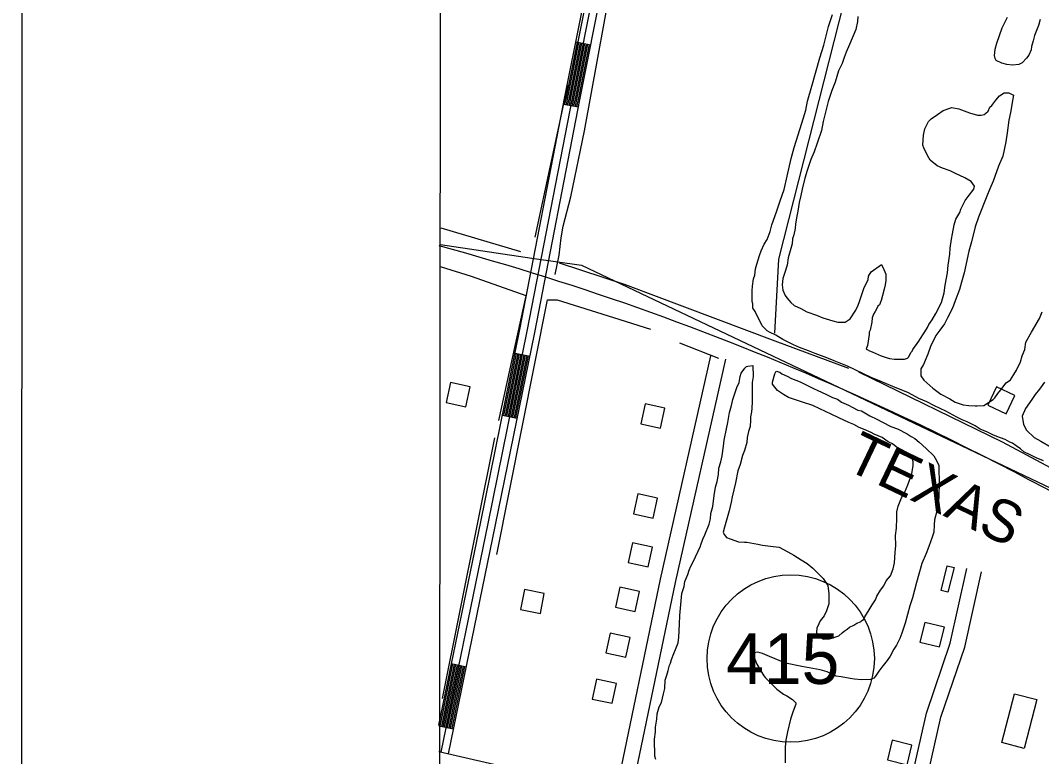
# Model space of a CAD drawing. Extents: x 3250478 to 3288318, y 788638 to 816472.
# Drawn here: x 3253812 to 3255826, y 797765 to 799216 of the extents above; entities that cross this region are included whole.
import ezdxf

# ---------------------------------------------------------------- set-up
doc = ezdxf.new("R2010")
doc.units = 0
for name, color, linetype in [('V-ANNO-SYMB', 7, 'Continuous'), ('V-BLDG-OTLN', 7, 'Continuous'), ('V-GRID-FRAM', 7, 'Continuous'), ('V-RAIL-IDEN', 7, 'Continuous'), ('V-RAIL-TRAK', 7, 'Continuous'), ('V-ROAD-CNTR', 7, 'Continuous'), ('V-ROAD-IDEN', 7, 'Continuous'), ('V-SITE-VEGE', 7, 'Continuous'), ('V-TOPO-SHOR', 7, 'Continuous')]:
    doc.layers.add(name, color=color, linetype=linetype)

msp = doc.modelspace()

# ---------------------------------------------------------------- linework, layer by layer
at = {"layer": 'V-ANNO-SYMB'}
msp.add_lwpolyline([(3253811.8, 789856.3), (3286895, 789846.6), (3286901.6, 812763.2), (3253818.4, 812772.8), (3253811.8, 789856.3)], dxfattribs=at)
at = {"layer": 'V-BLDG-OTLN'}
for points in [[(3254690.2, 798454.9), (3254698.8, 798494), (3254659.7, 798502.5), (3254651.1, 798463.4)], [(3255719.5, 798458.1), (3255755.7, 798441.1), (3255772.7, 798477.3), (3255736.5, 798494.3)], [(3255074.2, 798412.9), (3255082.7, 798452), (3255043.7, 798460.5), (3255035.1, 798421.4)], [(3255059.7, 798235.5), (3255068.2, 798274.6), (3255029.2, 798283.1), (3255020.6, 798244.1)], [(3255049.6, 798139.3), (3255058.1, 798178.4), (3255019.1, 798186.9), (3255010.5, 798147.9)], [(3255627.4, 798092.9), (3255639.3, 798141.5), (3255652.9, 798138.2), (3255641, 798089.6)], [(3254805.6, 798094.6), (3254798, 798055.3), (3254837.3, 798047.7), (3254844.9, 798087)], [(3255024.1, 798051.5), (3255032.7, 798090.6), (3254993.6, 798099.1), (3254985.1, 798060)], [(3255624.5, 797981.5), (3255634.1, 798020.3), (3255595.3, 798030), (3255585.6, 797991.1)], [(3255005.5, 797961.2), (3255014.1, 798000.3), (3254975, 798008.8), (3254966.5, 797969.8)], [(3254978.6, 797870.4), (3254987.2, 797909.5), (3254948.1, 797918), (3254939.6, 797878.9)], [(3255747, 797793), (3255772.3, 797889.3), (3255816.4, 797877.8), (3255791.1, 797781.4)], [(3255560.4, 797749), (3255570, 797787.9), (3255531.2, 797797.5), (3255521.6, 797758.7)]]:
    msp.add_lwpolyline(points, close=True, dxfattribs=at)
at = {"layer": 'V-GRID-FRAM'}
msp.add_lwpolyline([(3254649.6, 812209.1), (3286070.1, 812200), (3286072.7, 794013.5), (3254636.4, 794022.7), (3254649.6, 812209.1)], dxfattribs=at)
at = {"layer": 'V-RAIL-TRAK'}
msp.add_line((3255451.1, 798480.9), (3256028, 798207), dxfattribs=at)
for points in [[(3254639.9, 798774.5), (3254820.5, 798748)], [(3254820.5, 798748), (3254918.5, 798733.7), (3255451.1, 798480.9)]]:
    msp.add_lwpolyline(points, dxfattribs=at)
at = {"layer": 'V-ROAD-CNTR'}
for p, q in [((3254907.2, 799174.2), (3254936.6, 799168.3)), ((3254882.8, 799051.5), (3254912.2, 799045.8)), ((3254787.3, 798560.8), (3254816.7, 798554.8)), ((3254762.3, 798438.4), (3254791.7, 798432.4)), ((3254661.9, 797948.6), (3254691.3, 797942.5)), ((3254637, 797826.1), (3254666.1, 797820.1))]:
    msp.add_line(p, q, dxfattribs=at)
for points in [[(3254637, 797827.5), (3254719.5, 798228.1), (3254796.7, 798606.9), (3254885.6, 799065.9), (3254977.9, 799527.7), (3255097.9, 800111.1), (3255272.1, 801014.2)], [(3254641.3, 797774.2), (3254734.2, 798225.1), (3254811.4, 798604), (3254900.3, 799063), (3254992.6, 799524.7), (3255112.7, 800108.2), (3255286.8, 801011.4)], [(3254656, 797771.1), (3254748.9, 798222.1), (3254826.1, 798601.1), (3254915, 799060.1), (3255007.3, 799521.7), (3255127.4, 800105.2), (3255301.6, 801008.5)], [(3254885.7, 799050.9), (3254888.5, 799065.3), (3254910.2, 799173.6)], [(3254888.7, 799050.3), (3254891.4, 799064.7), (3254913.1, 799173)], [(3254891.6, 799049.8), (3254894.4, 799064.1), (3254916, 799172.4)], [(3254894.6, 799049.2), (3254897.3, 799063.6), (3254919, 799171.8)], [(3254897.5, 799048.6), (3254900.3, 799063), (3254921.9, 799171.2)], [(3254900.4, 799048.1), (3254903.2, 799062.4), (3254924.9, 799170.6)], [(3254903.4, 799047.5), (3254906.2, 799061.8), (3254927.8, 799170)], [(3254906.3, 799046.9), (3254909.1, 799061.2), (3254930.8, 799169.5)], [(3254909.3, 799046.3), (3254912.1, 799060.7), (3254933.7, 799168.9)], [(3254765.3, 798437.8), (3254790.3, 798560.2)], [(3254768.2, 798437.2), (3254793.2, 798559.6)], [(3254771.2, 798436.6), (3254796.1, 798559)], [(3254774.1, 798436), (3254799.1, 798558.4)], [(3254777, 798435.4), (3254802, 798557.8)], [(3254780, 798434.8), (3254805, 798557.2)], [(3254782.9, 798434.2), (3254807.9, 798556.6)], [(3254785.9, 798433.6), (3254810.8, 798556)], [(3254788.8, 798433), (3254813.8, 798555.4)], [(3255172.8, 798555.4), (3255073.6, 798114.9), (3254986.1, 797694.9)], [(3255202.1, 798548.8), (3255102.9, 798108.5), (3255015.5, 797688.8)], [(3255536, 797575.4), (3255598.3, 797850.9), (3255645, 797989.1), (3255678, 798136.4)], [(3255565.3, 797568.8), (3255627.2, 797842.8), (3255674, 797981), (3255707.3, 798129.8)], [(3254639.6, 797825.5), (3254664.8, 797948)], [(3254642.6, 797824.9), (3254667.8, 797947.4)], [(3254645.5, 797824.3), (3254670.7, 797946.8)], [(3254648.4, 797823.7), (3254673.7, 797946.2)], [(3254651.4, 797823.1), (3254676.6, 797945.6)], [(3254654.3, 797822.5), (3254679.5, 797944.9)], [(3254657.2, 797821.9), (3254682.5, 797944.3)], [(3254660.2, 797821.3), (3254685.4, 797943.7)], [(3254663.1, 797820.7), (3254688.3, 797943.1)], [(3254636.9, 797775.2), (3254947.7, 797703.6), (3255403.4, 797603), (3255700, 797540.9)]]:
    msp.add_lwpolyline(points, dxfattribs=at)
for centre, radius, start, end in [((3253165.2, 793365.4), 5603.5, 65.816, 74.7649), ((3252927.2, 792861), 6161.2, 55.44711, 65.71922)]:
    msp.add_arc(centre, radius, start, end, dxfattribs=at)
at = {"layer": 'V-ROAD-IDEN'}
msp.add_circle((3255330.8, 797958.6), 165, dxfattribs=at)
msp.add_circle((3255330.8, 797958.6), 165, dxfattribs=at)
at = {"layer": 'V-SITE-VEGE'}
for points in [[(3255829.3, 798348.1), (3255814.9, 798354.2), (3255803.2, 798360.3), (3255790.6, 798366.4), (3255784.3, 798371.7), (3255775.3, 798377.9), (3255768.1, 798383.1), (3255762.7, 798384.9), (3255753.7, 798390.1), (3255744.7, 798393.6), (3255737.5, 798396.2), (3255729.4, 798399.7), (3255718.7, 798404.9), (3255704.3, 798411), (3255694.4, 798417.2), (3255679.1, 798425), (3255669.2, 798429.4), (3255658.4, 798434.6), (3255636.8, 798446), (3255614.3, 798456.5), (3255599, 798464.4), (3255583.7, 798471.3), (3255563, 798482.7), (3255532.5, 798494.9), (3255507.3, 798505.3), (3255489.4, 798512.3), (3255442.6, 798535), (3255416.5, 798545.4), (3255402.1, 798551.5), (3255378.8, 798560.2), (3255366.2, 798565.4), (3255348.3, 798571.5), (3255336.6, 798576.7), (3255315, 798587.2), (3255301.5, 798596), (3255288.9, 798602.1), (3255284.4, 798604.7), (3255274.4, 798614.4), (3255260.7, 798642.9), (3255258, 798646.4), (3255256.1, 798649.1), (3255256, 798658.1), (3255255.1, 798662.5), (3255254.9, 798683.1), (3255255.6, 798692.9), (3255257.3, 798707.3), (3255259.9, 798714.4), (3255261.5, 798727), (3255264.1, 798736), (3255269.2, 798753), (3255272.7, 798762), (3255278.8, 798775.5), (3255284.1, 798784.5), (3255290.2, 798800.6), (3255293.6, 798813.2), (3255303.1, 798839.3), (3255310, 798860.8), (3255317.8, 798883.2), (3255323.8, 798909.3), (3255331.4, 798944.2), (3255337.4, 798965.8), (3255353, 799014.2), (3255360.7, 799039.4), (3255364.1, 799057.3), (3255372.7, 799086.9), (3255388.2, 799142.5), (3255395.9, 799167.7), (3255405.3, 799204.4), (3255413.1, 799227.8)], [(3255463.2, 799223.9), (3255462.5, 799214), (3255459.1, 799198.8), (3255446.9, 799169.1), (3255439.9, 799153.9), (3255436.5, 799143.1), (3255432.1, 799131.4), (3255425.1, 799117), (3255418.2, 799094.6), (3255412.2, 799078.4), (3255404.4, 799056.9), (3255395, 799017.4), (3255391.6, 798999.5), (3255383, 798974.3), (3255376.9, 798957.3), (3255370.8, 798942), (3255363, 798920.4), (3255358.7, 798905.2), (3255353.6, 798883.7), (3255351.1, 798871.1), (3255347.6, 798857.7), (3255345.1, 798840.6), (3255342.6, 798830.8), (3255340.1, 798815.5), (3255339.3, 798806.6), (3255336.7, 798794), (3255334.2, 798786), (3255333.4, 798776.1), (3255330.8, 798767.1), (3255325.6, 798748.3), (3255324, 798734), (3255318.8, 798717.8), (3255315.4, 798707.9), (3255313.7, 798695.4), (3255315.6, 798684.7), (3255320.2, 798674), (3255323, 798669.6), (3255331.1, 798660.7), (3255337.5, 798654.5), (3255350.9, 798648.4), (3255362.6, 798642.3), (3255381.5, 798635.4)], [(3255822.8, 799218.2), (3255819.4, 799206.5), (3255811.6, 799186.8), (3255809, 799176), (3255805.6, 799165.2), (3255804.8, 799158.1), (3255800.4, 799148.2), (3255796, 799141.9), (3255787.2, 799132.8), (3255780.9, 799129.2), (3255768.4, 799128.1), (3255756.8, 799129.8), (3255746.9, 799132.4), (3255736.1, 799137.6), (3255734.3, 799141.2), (3255732.4, 799147.4), (3255734.1, 799159.9), (3255737.5, 799171.6), (3255747.9, 799202.1), (3255758.4, 799222.8)], [(3255381.5, 798635.4), (3255394.1, 798630.1), (3255413.8, 798624.1), (3255423.7, 798621.5), (3255438, 798621.7), (3255444.2, 798625.3), (3255447.8, 798628.1), (3255459.2, 798645.2), (3255463.6, 798655.1), (3255466.2, 798662.3), (3255472.2, 798680.2), (3255475.7, 798690.1), (3255483.5, 798705.4), (3255484.4, 798712.6), (3255489.6, 798720.7), (3255510, 798735.2), (3255514.6, 798725.4), (3255518.3, 798716.5), (3255518.4, 798704), (3255516.8, 798695), (3255515.1, 798687), (3255511.6, 798674.4), (3255509.1, 798664.6), (3255505.6, 798655.6), (3255502.9, 798652.9), (3255500.3, 798647.5), (3255497.7, 798643), (3255494.2, 798637.6), (3255491.6, 798630.4), (3255490.8, 798621.4), (3255487.4, 798606.2), (3255485.6, 798601.7), (3255485.7, 798597.2), (3255482.4, 798575.7), (3255479.8, 798569.4), (3255481.6, 798567.6), (3255486.1, 798565), (3255491.4, 798563.3), (3255509.4, 798555.4), (3255519.3, 798552), (3255525.6, 798550.3), (3255535.4, 798548.6), (3255555.1, 798548.8), (3255561.4, 798550.7), (3255564, 798553.4), (3255565.7, 798557.9), (3255568.4, 798562.4), (3255570.1, 798564.2), (3255571.9, 798567.8), (3255583.3, 798584), (3255586.8, 798589.4), (3255593, 798598.4), (3255595.6, 798602.9), (3255600.9, 798611.1), (3255603.5, 798617.3), (3255609.7, 798626.4), (3255616.7, 798639), (3255628.1, 798660.6), (3255633.2, 798679.4), (3255635.7, 798694.6), (3255639.9, 798718.8), (3255641.5, 798734.1), (3255644.8, 798755.6), (3255645.6, 798767.2), (3255648.1, 798785.1), (3255649.7, 798795.9), (3255653.1, 798813.8), (3255656.6, 798824.6), (3255664.5, 798838.1), (3255666.2, 798844.3), (3255674.9, 798861.4), (3255681.1, 798869.6), (3255691.7, 798884), (3255693.4, 798889.4), (3255687, 798899.1), (3255674.4, 798906.1), (3255655.5, 798914.9), (3255645.6, 798920.1), (3255630.4, 798925.3), (3255619.6, 798929.7), (3255606, 798941.1), (3255600.6, 798950), (3255593.2, 798965.1), (3255591.4, 798970.5), (3255592.9, 798990.2), (3255595.5, 799002.7), (3255602.5, 799017.1), (3255607.8, 799022.5), (3255620.2, 799030.7), (3255631.7, 799038.9), (3255648.7, 799044.5), (3255662.1, 799041.9), (3255683.7, 799034.1), (3255698.9, 799029.8), (3255706.1, 799029.9), (3255712.3, 799030.9), (3255715.9, 799033.6), (3255720.3, 799037.3), (3255723.8, 799045.3), (3255727.3, 799049), (3255735.2, 799058.9)], [(3255735.2, 799058.9), (3255742.3, 799067.9), (3255752.1, 799073.4), (3255761, 799073.5), (3255770, 799069.1), (3255769.2, 799062), (3255764.1, 799035.1), (3255760.7, 799019.8), (3255757.5, 798994.8), (3255755, 798976.8), (3255749, 798949), (3255740.3, 798929.3), (3255729.9, 798899.6), (3255723.8, 798884.4), (3255717.8, 798870), (3255701.2, 798828.7), (3255694.3, 798809.8), (3255687.5, 798780.2), (3255682.3, 798761.4), (3255673, 798719.2), (3255667.8, 798700.4), (3255663.5, 798686), (3255654.9, 798663.6), (3255649.6, 798649.2), (3255640, 798630.3), (3255633.9, 798618.6), (3255625.1, 798606), (3255617.2, 798595.1), (3255606.7, 798573.6), (3255601.5, 798558.3), (3255592.8, 798538.5), (3255587.5, 798529.5), (3255587.7, 798516.1), (3255593.2, 798507.2), (3255611.2, 798491.3), (3255626.6, 798479.9), (3255644.6, 798470.3), (3255655.4, 798464.1), (3255670.6, 798458.9), (3255682.3, 798457.3), (3255694.8, 798456.5), (3255698.4, 798456.6), (3255711.8, 798457.6), (3255730.4, 798469.5), (3255733.1, 798472.2), (3255739.2, 798481.2), (3255745.4, 798488.4), (3255756, 798502), (3255764, 798508.3), (3255771, 798518.2), (3255776.3, 798527.2), (3255784.1, 798543.4), (3255787.6, 798555.1), (3255792.8, 798567.7), (3255794.4, 798582), (3255805.8, 798601.8), (3255821.6, 798628.8), (3255826.8, 798642.3)], [(3255128, 798124.1), (3255130.9, 798132.9), (3255133.7, 798140.7), (3255138.5, 798149.6), (3255152.8, 798180.1), (3255153.7, 798183), (3255157.5, 798193.8), (3255161.3, 798202.6), (3255169.9, 798223.3), (3255172.7, 798234), (3255173.6, 798244.8), (3255177.3, 798258.5), (3255180, 798280.1), (3255182.7, 798296.7), (3255185.5, 798307.5), (3255188.3, 798321.2), (3255189.1, 798333.9), (3255192.9, 798346.7), (3255195.7, 798358.4), (3255198.4, 798377), (3255199.3, 798388.8), (3255203.9, 798411.3), (3255206.7, 798424.1), (3255210.4, 798443.7), (3255214.1, 798457.4), (3255216.9, 798469.1), (3255224.4, 798492.7), (3255229.2, 798502.5), (3255231, 798514.3), (3255232.9, 798521.1), (3255240.6, 798531), (3255243.5, 798534), (3255246.4, 798535), (3255256.2, 798536.1), (3255256.5, 798514.6), (3255254.6, 798502.8), (3255255.1, 798464.7), (3255254.2, 798452), (3255253.3, 798445.1), (3255251.5, 798435.3), (3255251.6, 798428.5), (3255250.7, 798415.8), (3255247.9, 798406), (3255245.1, 798394.2), (3255244.3, 798384.4), (3255239.6, 798368.7), (3255235.8, 798358.9), (3255231.1, 798341.3), (3255226.3, 798328.5), (3255221.7, 798305), (3255215.2, 798277.5), (3255213.4, 798266.8), (3255209.7, 798250.1), (3255206.8, 798240.3), (3255203.1, 798226.6), (3255200.3, 798217.8), (3255197.4, 798207.9), (3255199.4, 798203.1), (3255204.4, 798197.3), (3255211.3, 798194.4), (3255228, 798188.7), (3255239.7, 798187.9), (3255244.6, 798188), (3255266.1, 798184.3), (3255274.9, 798182.4), (3255296.5, 798179.8), (3255308.2, 798177.9), (3255324.9, 798169.3), (3255336.8, 798162.6), (3255351.5, 798153), (3255363.3, 798146.3), (3255374.2, 798136.7), (3255395, 798116.4), (3255403.9, 798102.8), (3255406.1, 798086.2), (3255406.3, 798066.7), (3255401.6, 798052.9), (3255396.8, 798043.1), (3255389.1, 798033.2), (3255386.2, 798027.3), (3255382.4, 798018.5), (3255381.5, 798009.7), (3255383.6, 798002.9), (3255395.4, 797997.1), (3255407.1, 797997.3), (3255413.9, 797999.3), (3255425.6, 798003.4), (3255432.4, 798009.3), (3255436.2, 798012.3), (3255442.1, 798016.3), (3255446.9, 798020.2), (3255455.6, 798024.2), (3255461.5, 798028.2), (3255468.3, 798031.2), (3255470.2, 798033.2), (3255475.1, 798036.2), (3255477, 798041.1), (3255485.6, 798054.9), (3255491.3, 798064.7), (3255498.1, 798074.6), (3255500.9, 798081.5)], [(3255519.1, 798112), (3255527.8, 798121.8), (3255532.6, 798135.6), (3255535.3, 798147.3), (3255537.1, 798167.9), (3255537.9, 798181.6), (3255537.7, 798201.1), (3255539.4, 798215.8), (3255540.2, 798235.4), (3255540, 798248.1), (3255542.9, 798258.8), (3255549.5, 798275.5), (3255555.3, 798285.4), (3255561.9, 798301.1), (3255569.5, 798322.7), (3255572.2, 798339.3), (3255572.1, 798346.2), (3255570.1, 798354.9), (3255566.1, 798358.8), (3255558.2, 798365.6), (3255551.4, 798369.4), (3255538.6, 798376.1), (3255531.7, 798381.9), (3255522.8, 798385.7), (3255511, 798394.3), (3255495.3, 798401), (3255489.4, 798403.9), (3255474.6, 798410.5), (3255465.8, 798414.3), (3255455, 798420.1), (3255445.2, 798423.9), (3255425.5, 798433.4), (3255410.8, 798440.1), (3255388.2, 798450.6), (3255374.4, 798457.3), (3255353.8, 798463.9), (3255326.3, 798473.3), (3255316.5, 798479.1), (3255304.7, 798486.8), (3255299.7, 798493.6), (3255294.7, 798499.4), (3255294.7, 798503.3), (3255299.4, 798519.9), (3255302.3, 798524.9), (3255309.1, 798523), (3255313.1, 798520.1), (3255323.9, 798515.3), (3255332.7, 798510.6), (3255349.4, 798503.9), (3255360.2, 798499.1), (3255377, 798490.5), (3255382.9, 798487.7), (3255401.5, 798479.1), (3255413.3, 798473.4), (3255423.1, 798469.6), (3255431, 798463.8), (3255444.8, 798458.1), (3255451.7, 798454.3), (3255463.4, 798448.5), (3255470.3, 798446.7), (3255480.2, 798440.9), (3255487, 798437.1), (3255500.8, 798430.4), (3255511.6, 798424.6), (3255528.3, 798416), (3255541.1, 798411.3), (3255560.8, 798401.8), (3255568.6, 798396), (3255575.5, 798392.2), (3255584.4, 798385.4), (3255598.2, 798372.9), (3255613.1, 798358.4), (3255616, 798353.5), (3255623, 798339.9), (3255623.5, 798298.9), (3255622.7, 798286.2), (3255622.8, 798275.4), (3255620.1, 798259.7), (3255619.2, 798249), (3255614.5, 798232.3), (3255613.6, 798222.5), (3255612.8, 798207.9), (3255610, 798198), (3255603.4, 798179.4), (3255597.7, 798165.6), (3255589.1, 798146), (3255578.8, 798108.7), (3255571.3, 798078.4), (3255565.7, 798062.7), (3255556.3, 798028.3), (3255549.7, 798008.7), (3255545.9, 797997.9), (3255539.2, 797985.1), (3255534.4, 797977.3), (3255526.7, 797963.5), (3255521, 797954.6), (3255510.4, 797941.8), (3255504.6, 797933.9), (3255497.9, 797924.1), (3255495, 797920.1), (3255488.2, 797917.1)], [(3255831.1, 798503.7), (3255821.4, 798489.3), (3255812.6, 798479.4), (3255806.4, 798469.4), (3255794.1, 798451.4), (3255787.2, 798436.1), (3255790, 798420.1), (3255795.5, 798408.5), (3255810.9, 798394.4), (3255824.4, 798387.4), (3255844.2, 798375.1)], [(3255064.8, 797759.7), (3255062.8, 797766.5), (3255062.4, 797799.8), (3255064.2, 797814.5), (3255064.1, 797823.3), (3255066.8, 797838.9), (3255067.7, 797849.7), (3255071.4, 797863.4), (3255076.2, 797872.3), (3255079.9, 797888.9), (3255082.7, 797899.7), (3255083.5, 797916.3), (3255086.3, 797926.1), (3255089.2, 797935), (3255092, 797945.8), (3255093.9, 797949.7), (3255095.8, 797956.5), (3255100.5, 797968.3), (3255103.4, 797976.2), (3255109.1, 797989.9), (3255109.9, 798000.7), (3255111.6, 798026.1), (3255112.3, 798043.7), (3255114.9, 798072.1), (3255115.8, 798086.8), (3255120.5, 798100.5), (3255122.3, 798110.3), (3255128, 798124.1)], [(3255500.9, 798081.5), (3255507.6, 798093.3), (3255514.4, 798102.1), (3255519.1, 798112)], [(3255488.2, 797917.1), (3255470.6, 797916.9), (3255456.9, 797917.7), (3255448.1, 797919.6), (3255430.4, 797922.3), (3255420.6, 797924.1), (3255402.9, 797932.7), (3255389.2, 797936.5), (3255374.5, 797939.2), (3255353, 797942.9), (3255320.6, 797949.4), (3255315.7, 797951.3), (3255300, 797957.9), (3255289.2, 797962.7), (3255275.5, 797968.4), (3255265.7, 797971.2), (3255258.8, 797970.2), (3255256.9, 797967.2), (3255257, 797961.3), (3255260, 797957.5), (3255264, 797947.7), (3255270, 797938), (3255277.9, 797924.4), (3255280.9, 797920.6), (3255303.6, 797898.3), (3255316.5, 797888.7), (3255323.3, 797884.9), (3255334.2, 797878.2), (3255341.1, 797871.4), (3255341.1, 797868.5), (3255335.4, 797854.7), (3255330.7, 797839), (3255324.2, 797814.5), (3255321.4, 797797.9), (3255319.6, 797784.2), (3255320, 797752.9)]]:
    msp.add_lwpolyline(points, dxfattribs=at)
at = {"layer": 'V-TOPO-SHOR'}
for p, q in [((3254826.7, 798789.2), (3254891.3, 799088.9)), ((3254640.7, 798807.3), (3254798.2, 798760.8)), ((3255111.6, 798581.2), (3255188.3, 798550.5)), ((3254643.9, 797880), (3254747.5, 798393.5))]:
    msp.add_line(p, q, dxfattribs=at)
for points in [[(3254901.7, 799125), (3254971.5, 799473.8), (3255056.9, 799920.7), (3255111.3, 800238.4), (3255142.3, 800349.5), (3254749.6, 800414.2), (3254667, 800429.7)], [(3254924, 798999), (3255054.5, 799711.9), (3255185, 800336.5), (3255330.6, 800394), (3255445.6, 800432.3), (3255468.6, 800439.9)], [(3255299.4, 798600.3), (3255307.2, 798746), (3255525.9, 799604.4), (3255698.5, 800367), (3255756.1, 800413)], [(3254866.4, 798715.4), (3254874.1, 798753.8), (3254877.9, 798788.2), (3254881.8, 798811.2), (3254897.1, 798868.7), (3254924, 798999)], [(3254874.1, 798738.4), (3255004.4, 798696.2), (3255299.4, 798585), (3255445.1, 798531.3)], [(3254755.2, 798428), (3254808.9, 798673.3), (3254701.6, 798711.6), (3254640.3, 798730.8)], [(3254751.3, 798163.6), (3254851.1, 798665.6), (3254870.2, 798665.6), (3254981.3, 798631.1), (3255054.2, 798608.1)], [(3255464.2, 798523.6), (3255747.8, 798385.6), (3255920.2, 798293.5), (3256039, 798220.7)]]:
    msp.add_lwpolyline(points, dxfattribs=at)

# ---------------------------------------------------------------- texts
at = {"layer": 'V-RAIL-IDEN'}
msp.add_text('TEXAS', height=83, rotation=334.5029, dxfattribs=at).set_placement((3255434.9, 798333.8))
at = {"layer": 'V-ROAD-IDEN'}
msp.add_text('415', height=100, rotation=360, dxfattribs=at).set_placement((3255203.6, 797908.6))

doc.saveas('drawing.dxf')
